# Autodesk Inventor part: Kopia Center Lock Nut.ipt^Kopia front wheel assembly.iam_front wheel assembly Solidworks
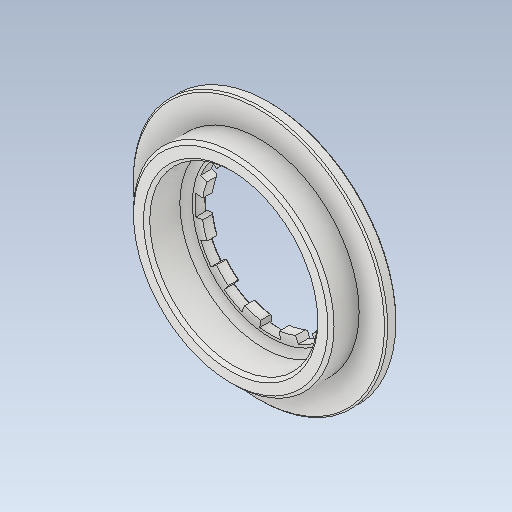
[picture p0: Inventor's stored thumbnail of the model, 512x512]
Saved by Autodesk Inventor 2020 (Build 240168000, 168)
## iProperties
Created: 2017-09
Part Number: Kopia Center Lock Nut.ipt^Kopia front wheel assembly.iam_front wheel assembly Solidworks
Material: Ogólny
Document SubType Name: Modeling
Designer: Tomasz
Density: 1 g/cm^3
Appearance: Domyślna
Sending System: SolidWorks 2017
Last Author: Tomasz
Last Saved: 2017-09-11
Author: Tomasz
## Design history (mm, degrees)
feature "Center Lock Nut.ipt"
node "Bryła1"
